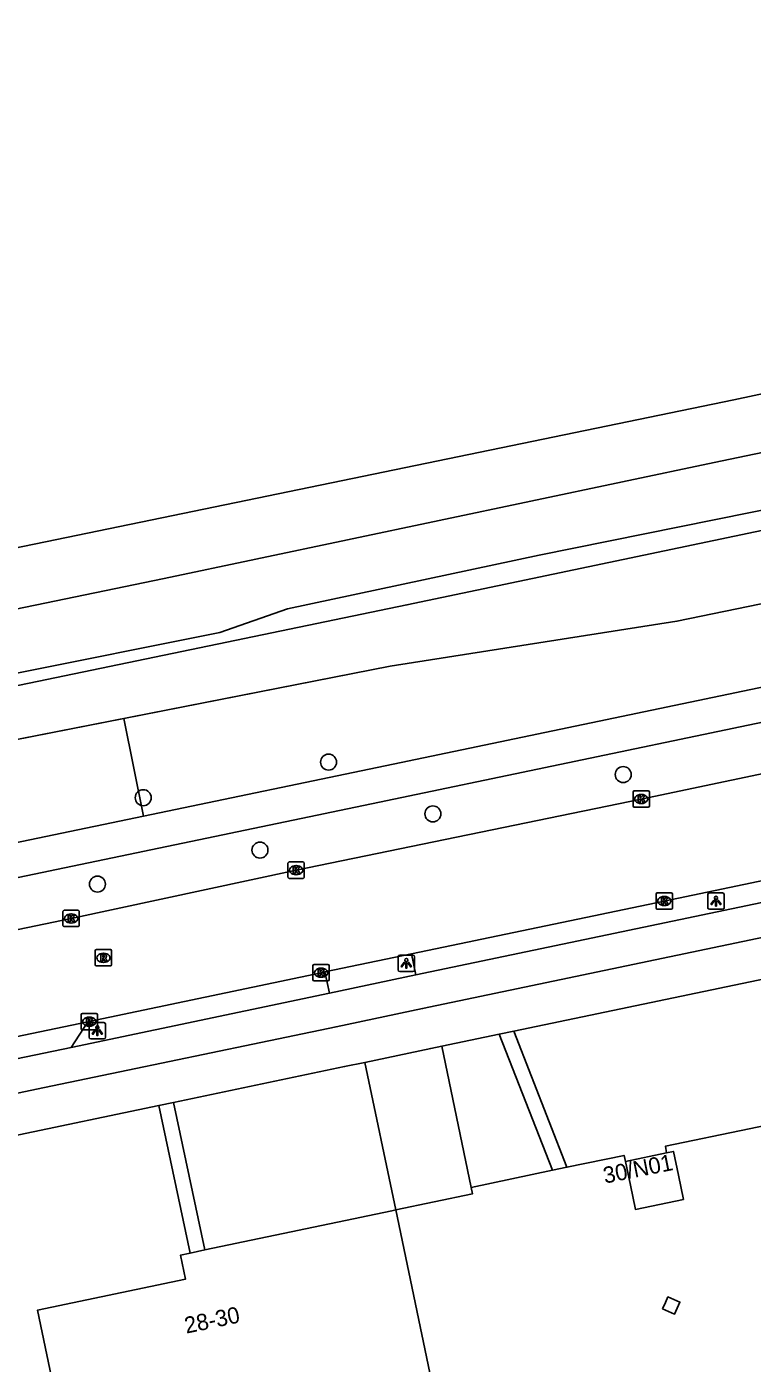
# Model space of a CAD drawing. Extents: x 164494 to 166241, y 382475 to 384494.
# Drawn here: x 164977.7 to 165022, y 384325.2 to 384407 of the extents above; entities that cross this region are included whole.
import ezdxf

# ---------------------------------------------------------------- set-up
doc = ezdxf.new("R2010")
doc.units = 0
for name, color, linetype in [('IMGEO_Boom', 7, 'Continuous'), ('IMGEO_Fietspad_open', 7, 'Continuous'), ('IMGEO_Greppel_droge_sloot', 7, 'Continuous'), ('IMGEO_Groenvoorziening', 7, 'Continuous'), ('IMGEO_Hek', 7, 'Continuous'), ('IMGEO_Hoogspanningsmast', 7, 'Continuous'), ('IMGEO_Kolk', 7, 'Continuous'), ('IMGEO_Lichtpunt', 7, 'Continuous'), ('IMGEO_Pand', 7, 'Continuous'), ('IMGEO_Pand_nummerreeks', 7, 'Continuous'), ('IMGEO_Rijbaan_lokaal_open', 7, 'Continuous'), ('IMGEO_Rioolput', 7, 'Continuous'), ('IMGEO_Spoor', 7, 'Continuous'), ('IMGEO_Spoorbaan_halfverhard', 7, 'Continuous'), ('IMGEO_Struiken', 7, 'Continuous'), ('IMGEO_Voetpad_open', 7, 'Continuous')]:
    doc.layers.add(name, color=color, linetype=linetype)

msp = doc.modelspace()

# ---------------------------------------------------------------- linework, layer by layer
at = {"layer": 'IMGEO_Boom'}
for centre in [(164996.121, 384361.991), (165014.148, 384361.23), (164984.78, 384359.817), (165002.503, 384358.827), (164991.924, 384356.614), (164981.98, 384354.53)]:
    msp.add_circle(centre, 0.489, dxfattribs=at)
at = {"layer": 'IMGEO_Fietspad_open'}
for points in [[(165105.349, 384383.872), (165102.387, 384383.258), (165077.784, 384378.116), (165043.832, 384371.007), (165000.08, 384361.873), (164984.803, 384358.696)], [(164926.103, 384341.106), (164925.461, 384344.192), (164936.708, 384346.52), (164998.737, 384359.434), (165044.842, 384369.066), (165078.417, 384376.067), (165103.145, 384381.247)], [(165118.509, 384373.384), (165114.768, 384372.637), (165100.699, 384369.712), (165051.79, 384359.513), (165001.461, 384348.974)], [(165123.59, 384372.323), (165118.614, 384371.278), (165101.155, 384367.679), (165052.181, 384357.436), (165001.876, 384346.919), (164996.584, 384345.814), (164978.743, 384342.085), (164958.923, 384337.938), (164932.507, 384332.46), (164912.329, 384328.255), (164868.92, 384319.253), (164838.611, 384312.969), (164833.08, 384311.822), (164809.925, 384307.04), (164802.068, 384305.407)], [(164984.803, 384358.696), (164934.915, 384348.321), (164898.89, 384340.836), (164875.602, 384335.981), (164845.275, 384329.624), (164797.88, 384319.828), (164794.806, 384319.188)], [(164996.183, 384347.859), (164980.371, 384344.544)]]:
    msp.add_lwpolyline(points, dxfattribs=at)
at = {"layer": 'IMGEO_Greppel_droge_sloot'}
for points in [[(165104.993, 384388.454), (165106.065, 384389.82), (165106.003, 384390.697), (165105.583, 384391.703), (165104.253, 384391.797), (165094.853, 384389.829), (165092.786, 384389.521), (165090.64, 384389.08), (165088.711, 384388.988), (165086.738, 384389.38), (165085.335, 384389.341), (165083.775, 384389.121), (165040.998, 384380.02), (165000.91, 384371.603), (164912.198, 384353.222), (164815.807, 384332.872), (164812.064, 384331.961), (164811.065, 384331.621), (164810.561, 384331.362), (164810.234, 384331.045), (164809.929, 384330.437), (164809.818, 384329.948), (164809.989, 384329.284), (164810.161, 384329.041)], [(164983.603, 384364.664), (164999.896, 384367.862), (165017.437, 384370.613), (165038.566, 384374.957), (165060.537, 384379.313), (165104.508, 384388.354)], [(164983.603, 384364.664), (164950.027, 384358.074), (164862.281, 384339.951), (164810.161, 384329.041)]]:
    msp.add_lwpolyline(points, dxfattribs=at)
at = {"layer": 'IMGEO_Groenvoorziening'}
for points in [[(165128.463, 384361.866), (165121.194, 384360.319), (165097.67, 384355.369), (165074.224, 384350.422), (165049.402, 384345.197), (165032.09, 384341.677), (165016.726, 384338.497), (165016.804, 384338.097)], [(165014.284, 384337.57), (165014.207, 384337.944), (165010.705, 384337.217)], [(165009.823, 384337.034), (165004.849, 384335.984)]]:
    msp.add_lwpolyline(points, dxfattribs=at)
at = {"layer": 'IMGEO_Hek'}
for points in [[(164792.371, 384325.328), (164793.82, 384325.659), (164799.547, 384326.819), (164862.281, 384339.951), (164950.027, 384358.074), (164999.896, 384367.862), (165017.437, 384370.613), (165038.566, 384374.957), (165060.537, 384379.313), (165104.993, 384388.454), (165107.365, 384388.949), (165107.179, 384392.936), (165107.536, 384394.767)], [(165128.694, 384361.62), (165128.463, 384361.866), (165121.194, 384360.319), (165097.67, 384355.369), (165074.224, 384350.422), (165049.402, 384345.197), (165032.09, 384341.677), (165016.726, 384338.497), (165016.804, 384338.097)], [(165000.234, 384334.604), (165004.93, 384335.595), (165004.849, 384335.984), (165009.823, 384337.034), (165010.705, 384337.217), (165014.207, 384337.944), (165014.284, 384337.57)]]:
    msp.add_lwpolyline(points, dxfattribs=at)
at = {"layer": 'IMGEO_Hoogspanningsmast'}
msp.add_lwpolyline([(165016.562, 384328.557), (165016.73, 384328.939), (165016.883, 384329.29), (165017.616, 384328.969), (165017.295, 384328.236), (165016.562, 384328.557)], dxfattribs=at)
at = {"layer": 'IMGEO_Kolk'}
for p, q in [((165014.827, 384360.237), (165015.679, 384360.237)), ((165014.752, 384359.311), (165014.752, 384360.163)), ((165015.263, 384359.457), (165015.238, 384359.457)), ((165015.24, 384360.017), (165015.265, 384360.017)), ((165015.753, 384360.163), (165015.753, 384359.311)), ((165015.679, 384359.237), (165014.827, 384359.237)), ((164993.636, 384354.959), (164993.636, 384355.811)), ((164993.711, 384355.885), (164994.563, 384355.885)), ((164994.124, 384355.665), (164994.149, 384355.665)), ((164994.637, 384355.811), (164994.637, 384354.959)), ((164994.563, 384354.885), (164993.711, 384354.885)), ((164994.147, 384355.105), (164994.122, 384355.105)), ((165016.161, 384353.071), (165016.161, 384353.923)), ((165016.236, 384353.997), (165017.088, 384353.997)), ((165016.649, 384353.777), (165016.674, 384353.777)), ((165017.162, 384353.923), (165017.162, 384353.071)), ((164979.869, 384352.004), (164979.869, 384352.856)), ((164979.944, 384352.93), (164980.796, 384352.93)), ((164980.87, 384352.856), (164980.87, 384352.004)), ((165017.088, 384352.997), (165016.236, 384352.997)), ((165016.672, 384353.217), (165016.647, 384353.217)), ((164980.38, 384352.15), (164980.355, 384352.15)), ((164980.357, 384352.71), (164980.382, 384352.71)), ((164980.796, 384351.93), (164979.944, 384351.93)), ((164995.233, 384349.615), (164996.085, 384349.615)), ((164995.158, 384348.689), (164995.158, 384349.541)), ((164995.669, 384348.835), (164995.644, 384348.835)), ((164995.646, 384349.395), (164995.671, 384349.395)), ((164996.159, 384349.541), (164996.159, 384348.689)), ((164996.085, 384348.615), (164995.233, 384348.615)), ((164980.981, 384345.695), (164980.981, 384346.547)), ((164981.056, 384346.621), (164981.908, 384346.621)), ((164981.469, 384346.401), (164981.494, 384346.401)), ((164981.982, 384346.547), (164981.982, 384345.695)), ((164981.908, 384345.621), (164981.056, 384345.621)), ((164981.492, 384345.841), (164981.467, 384345.841))]:
    msp.add_line(p, q, dxfattribs=at)
for points in [[(165014.827, 384360.237), (165015.679, 384360.237)], [(165014.752, 384359.311), (165014.752, 384360.163)], [(165015.073, 384359.937), (165015.196, 384359.937), (165015.196, 384359.786), (165015.326, 384359.937), (165015.49, 384359.937), (165015.344, 384359.786), (165015.497, 384359.537), (165015.345, 384359.537), (165015.26, 384359.701), (165015.196, 384359.634), (165015.196, 384359.537), (165015.073, 384359.537), (165015.073, 384359.937)], [(165015.753, 384360.163), (165015.753, 384359.311)], [(165015.679, 384359.237), (165014.827, 384359.237)], [(164993.636, 384354.959), (164993.636, 384355.811)], [(164993.711, 384355.885), (164994.563, 384355.885)], [(164993.957, 384355.585), (164994.08, 384355.585), (164994.08, 384355.434), (164994.21, 384355.585), (164994.374, 384355.585), (164994.228, 384355.434), (164994.381, 384355.185), (164994.229, 384355.185), (164994.144, 384355.349), (164994.08, 384355.282), (164994.08, 384355.185), (164993.957, 384355.185), (164993.957, 384355.585)], [(164994.637, 384355.811), (164994.637, 384354.959)], [(164994.563, 384354.885), (164993.711, 384354.885)], [(165016.161, 384353.071), (165016.161, 384353.923)], [(165016.236, 384353.997), (165017.088, 384353.997)], [(165016.482, 384353.697), (165016.605, 384353.697), (165016.605, 384353.546), (165016.735, 384353.697), (165016.899, 384353.697), (165016.753, 384353.546), (165016.906, 384353.297), (165016.754, 384353.297), (165016.669, 384353.461), (165016.605, 384353.394), (165016.605, 384353.297), (165016.482, 384353.297), (165016.482, 384353.697)], [(165017.162, 384353.923), (165017.162, 384353.071)], [(164979.869, 384352.004), (164979.869, 384352.856)], [(164979.944, 384352.93), (164980.796, 384352.93)], [(164980.87, 384352.856), (164980.87, 384352.004)], [(165017.088, 384352.997), (165016.236, 384352.997)], [(164980.19, 384352.63), (164980.313, 384352.63), (164980.313, 384352.479), (164980.443, 384352.63), (164980.607, 384352.63), (164980.461, 384352.479), (164980.614, 384352.23), (164980.462, 384352.23), (164980.377, 384352.394), (164980.313, 384352.327), (164980.313, 384352.23), (164980.19, 384352.23), (164980.19, 384352.63)], [(164980.796, 384351.93), (164979.944, 384351.93)], [(164995.233, 384349.615), (164996.085, 384349.615)], [(164995.158, 384348.689), (164995.158, 384349.541)], [(164995.479, 384349.315), (164995.602, 384349.315), (164995.602, 384349.164), (164995.732, 384349.315), (164995.896, 384349.315), (164995.75, 384349.164), (164995.903, 384348.915), (164995.751, 384348.915), (164995.666, 384349.079), (164995.602, 384349.012), (164995.602, 384348.915), (164995.479, 384348.915), (164995.479, 384349.315)], [(164996.159, 384349.541), (164996.159, 384348.689)], [(164996.085, 384348.615), (164995.233, 384348.615)], [(164980.981, 384345.695), (164980.981, 384346.547)], [(164981.056, 384346.621), (164981.908, 384346.621)], [(164981.302, 384346.321), (164981.425, 384346.321), (164981.425, 384346.17), (164981.555, 384346.321), (164981.719, 384346.321), (164981.573, 384346.17), (164981.726, 384345.921), (164981.574, 384345.921), (164981.489, 384346.085), (164981.425, 384346.018), (164981.425, 384345.921), (164981.302, 384345.921), (164981.302, 384346.321)], [(164981.982, 384346.547), (164981.982, 384345.695)], [(164981.908, 384345.621), (164981.056, 384345.621)]]:
    msp.add_lwpolyline(points, dxfattribs=at)
for centre, start, end in [((165014.829, 384360.161), 91.55205, 178.44795), ((165014.829, 384360.161), 91.55205, 178.44795), ((165015.677, 384360.161), 1.55205, 88.44795), ((165015.677, 384360.161), 1.55205, 88.44795), ((165014.829, 384359.313), 181.55205, 268.44795), ((165014.829, 384359.313), 181.55205, 268.44795), ((165015.677, 384359.313), 271.55205, 358.44795), ((165015.677, 384359.313), 271.55205, 358.44795), ((164993.713, 384355.809), 91.55205, 178.44795), ((164993.713, 384355.809), 91.55205, 178.44795), ((164994.561, 384355.809), 1.55205, 88.44795), ((164994.561, 384355.809), 1.55205, 88.44795), ((164993.713, 384354.961), 181.55205, 268.44795), ((164993.713, 384354.961), 181.55205, 268.44795), ((164994.561, 384354.961), 271.55205, 358.44795), ((164994.561, 384354.961), 271.55205, 358.44795), ((165016.238, 384353.921), 91.55205, 178.44795), ((165016.238, 384353.921), 91.55205, 178.44795), ((165017.086, 384353.921), 1.55205, 88.44795), ((165017.086, 384353.921), 1.55205, 88.44795), ((164979.946, 384352.854), 91.55205, 178.44795), ((164979.946, 384352.854), 91.55205, 178.44795), ((164980.794, 384352.854), 1.55205, 88.44795), ((164980.794, 384352.854), 1.55205, 88.44795), ((165016.238, 384353.073), 181.55205, 268.44795), ((165016.238, 384353.073), 181.55205, 268.44795), ((165017.086, 384353.073), 271.55205, 358.44795), ((165017.086, 384353.073), 271.55205, 358.44795), ((164979.946, 384352.006), 181.55205, 268.44795), ((164979.946, 384352.006), 181.55205, 268.44795), ((164980.794, 384352.006), 271.55205, 358.44795), ((164980.794, 384352.006), 271.55205, 358.44795), ((164995.235, 384349.539), 91.55205, 178.44795), ((164995.235, 384349.539), 91.55205, 178.44795), ((164996.083, 384349.539), 1.55205, 88.44795), ((164996.083, 384349.539), 1.55205, 88.44795), ((164995.235, 384348.691), 181.55205, 268.44795), ((164995.235, 384348.691), 181.55205, 268.44795), ((164996.083, 384348.691), 271.55205, 358.44795), ((164996.083, 384348.691), 271.55205, 358.44795), ((164981.058, 384346.545), 91.55205, 178.44795), ((164981.058, 384346.545), 91.55205, 178.44795), ((164981.906, 384346.545), 1.55205, 88.44795), ((164981.906, 384346.545), 1.55205, 88.44795), ((164981.058, 384345.697), 181.55205, 268.44795), ((164981.058, 384345.697), 181.55205, 268.44795), ((164981.906, 384345.697), 271.55205, 358.44795), ((164981.906, 384345.697), 271.55205, 358.44795)]:
    msp.add_arc(centre, 0.0765, start, end, dxfattribs=at)
for centre, major_axis, ratio, start_param, end_param in [((165015.239, 384359.737), (-0.387, 0.002), 0.722429, 4.712389, 7.853982), ((165015.264, 384359.737), (-0.39, 0.002), 0.717154, 1.570796, 4.712389), ((164994.123, 384355.385), (-0.387, 0.002), 0.722429, 4.712389, 7.853982), ((164994.148, 384355.385), (-0.39, 0.002), 0.717154, 1.570796, 4.712389), ((165016.648, 384353.497), (-0.387, 0.002), 0.722429, 4.712389, 7.853982), ((165016.673, 384353.497), (-0.39, 0.002), 0.717154, 1.570796, 4.712389), ((164980.356, 384352.43), (-0.387, 0.002), 0.722429, 4.712389, 7.853982), ((164980.381, 384352.43), (-0.39, 0.002), 0.717154, 1.570796, 4.712389), ((164995.645, 384349.115), (-0.387, 0.002), 0.722429, 4.712389, 7.853982), ((164995.67, 384349.115), (-0.39, 0.002), 0.717154, 1.570796, 4.712389), ((164981.468, 384346.121), (-0.387, 0.002), 0.722429, 4.712389, 7.853982), ((164981.493, 384346.121), (-0.39, 0.002), 0.717154, 1.570796, 4.712389)]:
    msp.add_ellipse(centre, major_axis=major_axis, ratio=ratio, start_param=start_param, end_param=end_param, dxfattribs=at)
at = {"layer": 'IMGEO_Lichtpunt'}
for p, q in [((165019.328, 384353.896), (165019.328, 384353.089)), ((165019.328, 384353.896), (165019.328, 384353.089)), ((165020.23, 384353.991), (165019.422, 384353.991)), ((165020.23, 384353.991), (165019.422, 384353.991)), ((165020.324, 384353.089), (165020.324, 384353.896)), ((165020.324, 384353.089), (165020.324, 384353.896)), ((165019.422, 384352.995), (165020.23, 384352.995)), ((165019.422, 384352.995), (165020.23, 384352.995)), ((165000.38, 384350.09), (165000.38, 384349.283)), ((165000.38, 384350.09), (165000.38, 384349.283)), ((165001.282, 384350.185), (165000.474, 384350.185)), ((165001.282, 384350.185), (165000.474, 384350.185)), ((165001.376, 384349.283), (165001.376, 384350.09)), ((165001.376, 384349.283), (165001.376, 384350.09)), ((165000.474, 384349.189), (165001.282, 384349.189)), ((165000.474, 384349.189), (165001.282, 384349.189)), ((164981.475, 384345.97), (164981.475, 384345.163)), ((164981.475, 384345.97), (164981.475, 384345.163)), ((164982.377, 384346.065), (164981.569, 384346.065)), ((164982.377, 384346.065), (164981.569, 384346.065)), ((164982.471, 384345.163), (164982.471, 384345.97)), ((164982.471, 384345.163), (164982.471, 384345.97)), ((164981.569, 384345.069), (164982.377, 384345.069)), ((164981.569, 384345.069), (164982.377, 384345.069))]:
    msp.add_line(p, q, dxfattribs=at)
for points in [[(165019.702, 384353.56), (165019.741, 384353.532), (165019.553, 384353.27), (165019.515, 384353.297), (165019.702, 384353.56)], [(165019.804, 384353.512), (165019.851, 384353.512), (165019.851, 384353.19), (165019.804, 384353.19), (165019.804, 384353.512)], [(165019.914, 384353.532), (165019.952, 384353.559), (165020.139, 384353.297), (165020.1, 384353.269), (165019.914, 384353.532)], [(165000.754, 384349.754), (165000.793, 384349.726), (165000.605, 384349.464), (165000.567, 384349.491), (165000.754, 384349.754)], [(165000.856, 384349.706), (165000.903, 384349.706), (165000.903, 384349.384), (165000.856, 384349.384), (165000.856, 384349.706)], [(165000.966, 384349.726), (165001.004, 384349.753), (165001.191, 384349.491), (165001.152, 384349.463), (165000.966, 384349.726)], [(164981.849, 384345.634), (164981.888, 384345.606), (164981.7, 384345.344), (164981.662, 384345.371), (164981.849, 384345.634)], [(164981.951, 384345.586), (164981.998, 384345.586), (164981.998, 384345.264), (164981.951, 384345.264), (164981.951, 384345.586)], [(164982.061, 384345.606), (164982.099, 384345.633), (164982.286, 384345.371), (164982.247, 384345.343), (164982.061, 384345.606)]]:
    msp.add_lwpolyline(points, dxfattribs=at)
for centre in [(165019.827, 384353.694), (165000.879, 384349.888), (164981.974, 384345.768)]:
    msp.add_circle(centre, 0.0994, dxfattribs=at)
for centre, start, end in [((165019.422, 384353.896), 90, 180), ((165019.422, 384353.896), 90, 180), ((165020.23, 384353.896), 0, 90), ((165020.23, 384353.896), 0, 90), ((165019.422, 384353.089), 180, 270), ((165019.422, 384353.089), 180, 270), ((165020.23, 384353.089), 270, 0), ((165020.23, 384353.089), 270, 360), ((165000.474, 384350.09), 90, 180), ((165000.474, 384350.09), 90, 180), ((165001.282, 384350.09), 0, 90), ((165001.282, 384350.09), 0, 90), ((165000.474, 384349.283), 180, 270), ((165000.474, 384349.283), 180, 270), ((165001.282, 384349.283), 270, 0), ((165001.282, 384349.283), 270, 360), ((164981.569, 384345.97), 90, 180), ((164981.569, 384345.97), 90, 180), ((164982.377, 384345.97), 0, 90), ((164982.377, 384345.97), 0, 90), ((164981.569, 384345.163), 180, 270), ((164981.569, 384345.163), 180, 270), ((164982.377, 384345.163), 270, 0), ((164982.377, 384345.163), 270, 360)]:
    msp.add_arc(centre, 0.0946, start, end, dxfattribs=at)
at = {"layer": 'IMGEO_Pand'}
for points in [[(165016.804, 384338.097), (165017.22, 384338.184), (165017.523, 384336.741), (165017.834, 384335.248), (165014.9, 384334.636), (165014.587, 384336.126), (165014.284, 384337.57)], [(165016.804, 384338.097), (165014.284, 384337.57)], [(165000.234, 384334.604), (165003.425, 384319.356), (165000, 384318.639), (164990.338, 384316.617), (164989.641, 384319.943), (164985.443, 384319.065)], [(165000.234, 384334.604), (165000, 384334.555), (164988.553, 384332.16)], [(164987.642, 384331.969), (164987.069, 384331.849), (164987.376, 384330.38), (164978.312, 384328.483), (164980.499, 384318.03), (164985.443, 384319.065)], [(164988.553, 384332.16), (164987.642, 384331.969)]]:
    msp.add_lwpolyline(points, dxfattribs=at)
at = {"layer": 'IMGEO_Rijbaan_lokaal_open'}
for points in [[(165103.841, 384378.298), (165103.18, 384378.131), (165082.552, 384373.828), (165059.459, 384368.999), (165037.346, 384364.383), (165015.253, 384359.737), (164994.137, 384355.385), (164980.37, 384352.43), (164954.306, 384347.035), (164933.216, 384342.574), (164926.103, 384341.106)], [(165001.186, 384350.268), (165016.662, 384353.497), (165038.786, 384358.11), (165060.866, 384362.734), (165083.93, 384367.513), (165118.108, 384374.601)], [(164995.895, 384349.164), (165001.186, 384350.268)], [(165001.186, 384350.268), (165001.461, 384348.974)], [(164981.397, 384346.103), (164981.482, 384346.121), (164995.659, 384349.115), (164995.895, 384349.164)], [(164995.895, 384349.164), (164996.183, 384347.859)], [(165001.461, 384348.974), (164996.183, 384347.859)], [(164955.712, 384340.765), (164981.397, 384346.103)], [(164980.371, 384344.544), (164981.397, 384346.103)], [(164980.371, 384344.544), (164956.926, 384339.68)], [(164998.345, 384343.632), (165002.371, 384344.482), (165003.041, 384344.622)], [(165004.849, 384335.984), (165003.041, 384344.622)], [(164998.345, 384343.632), (165000.234, 384334.604)], [(165004.849, 384335.984), (165004.93, 384335.595), (165000.234, 384334.604)]]:
    msp.add_lwpolyline(points, dxfattribs=at)
at = {"layer": 'IMGEO_Rioolput'}
for p, q in [((164981.841, 384349.599), (164981.841, 384350.451)), ((164981.916, 384350.525), (164982.768, 384350.525)), ((164982.842, 384350.451), (164982.842, 384349.599)), ((164982.352, 384349.745), (164982.327, 384349.745)), ((164982.329, 384350.305), (164982.354, 384350.305)), ((164982.768, 384349.525), (164981.916, 384349.525))]:
    msp.add_line(p, q, dxfattribs=at)
for points in [[(164981.841, 384349.599), (164981.841, 384350.451)], [(164981.916, 384350.525), (164982.768, 384350.525)], [(164982.842, 384350.451), (164982.842, 384349.599)], [(164982.43, 384350.223), (164982.178, 384350.225), (164982.178, 384349.825)], [(164982.178, 384349.825), (164982.302, 384349.825), (164982.302, 384349.987), (164982.313, 384349.987)], [(164982.356, 384350.144), (164982.302, 384350.144), (164982.302, 384350.063)], [(164982.302, 384350.063), (164982.354, 384350.063)], [(164982.36, 384349.958), (164982.431, 384349.825), (164982.571, 384349.825), (164982.506, 384349.951)], [(164982.768, 384349.525), (164981.916, 384349.525)]]:
    msp.add_lwpolyline(points, dxfattribs=at)
for centre, radius, start, end in [((164981.918, 384350.449), 0.0765, 91.55205, 178.44795), ((164981.918, 384350.449), 0.0765, 91.55205, 178.44795), ((164982.766, 384350.449), 0.0765, 1.55205, 88.44795), ((164982.766, 384350.449), 0.0765, 1.55205, 88.44795), ((164981.918, 384349.601), 0.0765, 181.55205, 268.44795), ((164981.918, 384349.601), 0.0765, 181.55205, 268.44795), ((164982.312, 384349.934), 0.0533, 26.02933, 88.69889), ((164982.338, 384350.252), 0.19, 274.7715, 282.96867), ((164982.362, 384350.048), 0.0964, 77.00612, 93.18647), ((164982.376, 384350.105), 0.0378, 276.66336, 79.67722), ((164982.429, 384350.113), 0.109, 350.36119, 89.41601), ((164982.427, 384350.113), 0.112, 277.58423, 350.98172), ((164982.411, 384349.898), 0.108, 29.51342, 73.79051), ((164982.766, 384349.601), 0.0765, 271.55205, 358.44795), ((164982.766, 384349.601), 0.0765, 271.55205, 358.44795)]:
    msp.add_arc(centre, radius, start, end, dxfattribs=at)
for centre, major_axis, ratio, start_param, end_param in [((164982.328, 384350.025), (-0.387, 0.002), 0.722429, 4.712389, 7.853982), ((164982.353, 384350.025), (-0.39, 0.002), 0.717154, 1.570796, 4.712389)]:
    msp.add_ellipse(centre, major_axis=major_axis, ratio=ratio, start_param=start_param, end_param=end_param, dxfattribs=at)
at = {"layer": 'IMGEO_Spoor'}
for points in [[(165534.642, 384491.339), (165527.155, 384489.842), (165498.336, 384483.749), (165300.848, 384442.555), (165180.102, 384417.538), (165154.253, 384412.052), (165058.779, 384392.205), (165020.911, 384384.156), (164953.473, 384370.243), (164918.38, 384362.867), (164827.656, 384344.031), (164796.154, 384337.413), (164788.231, 384335.773)], [(165535.404, 384487.554), (165347.592, 384448.533), (165284.368, 384435.3), (165189.312, 384415.622), (165019.715, 384380.308), (164986.051, 384373.23), (164945.984, 384364.945), (164850.572, 384344.992), (164797.73, 384334.115), (164789.572, 384332.389)]]:
    msp.add_lwpolyline(points, dxfattribs=at)
at = {"layer": 'IMGEO_Spoorbaan_halfverhard'}
msp.add_lwpolyline([(164796.468, 384328.762), (164809.794, 384332.027), (164812.313, 384333.001), (164815.919, 384334.01), (164826.252, 384336.209), (164847.742, 384340.431), (164860.86, 384343.215), (164877.535, 384347.017), (164920.34, 384355.646), (164963.792, 384364.777), (164989.47, 384369.926), (164993.61, 384371.368), (165009.016, 384374.65), (165030.52, 384378.991), (165047.947, 384382.37), (165057.819, 384384.438), (165069.605, 384387.142), (165081.406, 384389.702), (165082.707, 384390.536), (165089.022, 384391.879)], dxfattribs=at)
at = {"layer": 'IMGEO_Struiken'}
msp.add_lwpolyline([(164984.803, 384358.696), (164983.603, 384364.664)], dxfattribs=at)
at = {"layer": 'IMGEO_Voetpad_open'}
for points in [[(165007.446, 384345.541), (165052.6, 384354.959), (165101.82, 384365.255), (165121.469, 384369.317)], [(165006.564, 384345.357), (165007.446, 384345.541)], [(165007.446, 384345.541), (165010.705, 384337.217)], [(165003.041, 384344.622), (165006.564, 384345.357)], [(165009.823, 384337.034), (165006.564, 384345.357)], [(164986.639, 384341.182), (164997.097, 384343.369), (164998.345, 384343.632)], [(164976.708, 384339.106), (164976.791, 384339.123), (164985.728, 384340.992)], [(164985.728, 384340.992), (164986.639, 384341.182)], [(164985.728, 384340.992), (164987.642, 384331.969)], [(164988.553, 384332.16), (164986.639, 384341.182)], [(165010.705, 384337.217), (165009.823, 384337.034)]]:
    msp.add_lwpolyline(points, dxfattribs=at)

# ---------------------------------------------------------------- texts
at = {"layer": 'IMGEO_Pand_nummerreeks'}
for s, rotation, p in [('30/N01', 11.25289, (165013.028, 384336.212)), ('28-30', 11.82078, (164987.414, 384327.037))]:
    msp.add_text(s, height=1, rotation=rotation, dxfattribs=at).set_placement(p)

doc.saveas('drawing.dxf')
